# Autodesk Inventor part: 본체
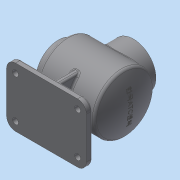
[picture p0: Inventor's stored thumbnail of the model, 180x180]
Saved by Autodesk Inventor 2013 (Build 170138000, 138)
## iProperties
Created: 2016-09
Part Number: 본체
Material: 일반
Document SubType Name: Modeling
Designer: dgall
Density: 1 g/cm^3
Author: dgall
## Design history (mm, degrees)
sketch "스케치1"
  geometry: L1 (-62, 0)-(60, 0); L2 (-62, 27)-(-47, 27); L3 (-47, 27)-(-47, 47); L4 (-47, 47)-(46.661, 47); L5 (-62, 27)-(-62, 38); L6 (-62, 38)-(-50, 38); L7 (-50, 38)-(-50, 50); L8 (-50, 50)-(48.562, 50); A1 r 115 centre (-55, 0) between (60, 0) and (48.562, 50); A2 r 112 centre (-55, 0) between (57, 0) and (46.661, 47); 2 further points
  constraints: 16 end point, 4 parallel, 4 point on circle, 3 perpendicular, 2 centre point, 2 point on line, 1 horizontal, 1 horizontal alignment, 1 midpoint
  dimensions: "d0" = 122 distance of L1.start L1.end; "d2" = 62 distance of L1.start point (0, 0); "d3" = 15 distance of L2.start L2.end; "d4" = 12 distance of L5.end L6.end; "d5" = 110 distance from line of L7 L1.end; "d6" = 76 diameter of L6 L1; "d7" = 54 diameter of L2 L1; "d8" = 100 diameter of L8 L1; "d9" = 94 diameter of L4 L1; "d10" = 230 diameter of A1; "d11" = 3 radial gap between concentric circles of A1 A2
revolve "회전1" sketch "스케치1" stored, may be unused: angle "d12" = 90 deg
sketch "스케치2" dims "d13" = 65
  geometry: C1 r 38 at (0, 0) reference; C2 r 27 at (0, 0) reference; 2 further points
  constraints: 2 vertical alignment, 1 coincident, 2 other
hole "구멍1" sketch "스케치2" at (0, 32.5) diameter "d15" = 3.242; stored, may be unused: countersink angle "d19" = 82 deg, drill point angle "d21" = 118 deg; dims "d16" = 8, "d17" = 3.023, "d18" = 2, "d20" = 10
node "작업 평면1"
sketch "스케치3" dims "d28" = 65
  geometry: C1 r 38 at (0, 0); C2 r 27 at (0, 0); 2 further points
  constraints: 2 centre point, 2 vertical alignment, 1 coincident, 2 other
  dimensions: "d26" = 76 diameter of C1; "d29" = 54 diameter of C2
extrude "돌출1" join sketch "스케치3" stored distance "d30" = 10; taper "d31" = 0 deg
extrude "돌출2" cut sketch "스케치3" distance "d32" = 61.5; taper "d33" = 0 deg
hole "구멍2" sketch "스케치3" diameter "d34" = 3.242; stored, may be unused: countersink angle "d38" = 82 deg, drill point angle "d40" = 118 deg; dims "d35" = 8, "d36" = 3.023, "d37" = 2, "d39" = 10
fillet "모깎기1" dims "d44" = 2
node "작업 평면2"
sketch "스케치4"
  geometry: L1 (67.5, 50)-(-67.5, 50); L2 (-67.5, 50)-(-67.5, -50); L3 (-67.5, -50)-(67.5, -50); L4 (67.5, -50)-(67.5, 50); 3 further points
  constraints: 8 end point, 2 midpoint, 2 parallel, 1 horizontal, 1 horizontal alignment, 1 perpendicular, 1 vertical alignment
  dimensions: "d46" = 135 distance of L2.end L3.end; "d48" = 100 distance of L3.end L1.start
extrude "돌출3" join sketch "스케치4" distance "d49" = 10; taper "d50" = 0 deg
fillet "모깎기2" dims "d51" = 15, "d52" = 5, "d53" = 3
sketch "스케치5"
  geometry: C1 r 5 at (-52.5, 35); C2 r 5 at (-52.5, -35); C3 r 5 at (52.5, -35); C4 r 5 at (52.5, 35); A1 r 15 centre (52.5, 35) between (67.5, 35) and (52.5, 50) reference; A2 r 15 centre (-52.5, 35) between (-52.5, 50) and (-67.5, 35) reference; A3 r 15 centre (-52.5, -35) between (-67.5, -35) and (-52.5, -50) reference; A4 r 15 centre (52.5, -35) between (52.5, -50) and (67.5, -35) reference; 1 further point
  constraints: 4 centre point, 4 coincident, 3 equal radius
  dimensions: "d54" = 10 diameter of C2
extrude "돌출4" cut sketch "스케치5" distance "d56" = 47.25; taper "d57" = 0 deg
sketch "스케치6"
  geometry: L1 (-72, 40)-(-72, 30) reference; L2 (-72, -30)-(-72, -40) reference; L3 (-72, 40)-(-72, 30) reference; L4 (-72, -30)-(-72, -40) reference; L5 (-72, -50)-(-72, -35) reference; L6 (-72, -35)-(-72, -50) reference; L7 (-72, -35)-(-72, 35) reference; L8 (-72, 50)-(-72, 35) reference; L9 (-72, 35)-(-72, 50) reference; L10 (-72, 35)-(-72, -35) reference; L11 (-30, 40)-(-72, 40); L12 (-30, -40)-(-72, -40); L13 (-72, 40)-(-72, -40); A1 r 50 centre (0, 0) between (-30, 40) and (-30, -40) reference; A2 r 50 centre (0, 0) between (-30, 40) and (-30, -40); 1 further point
  constraints: 6 end point, 4 point on circle, 3 perpendicular, 2 point on line, 1 centre point, 1 coincident, 1 concentric, 1 parallel
  dimensions: "d58" = 40 distance from line of point (0, 0) L12
extrude "돌출5" join sketch "스케치6" stored distance "d59" = 10; taper "d60" = 0 deg
sketch "스케치7"
  geometry: L1 (-45, -50)-(45.374, -50) reference; L2 (52.5, -72)-(-52.5, -72) reference; L3 (52.5, -72)-(67.5, -72) reference; L4 (67.5, -72)-(67.5, -82) reference; L5 (67.5, -82)-(52.5, -82) reference; L6 (52.5, -82)-(52.5, -72) reference; L7 (-67.5, -72)-(-52.5, -72) reference; L8 (-52.5, -72)-(-52.5, -82) reference; L9 (-52.5, -82)-(-67.5, -82) reference; L10 (-67.5, -82)-(-67.5, -72) reference; L11 (-40, -72)-(-37.988, -49); L12 (-37.988, -49)-(37.988, -49); L13 (37.988, -49)-(40, -72); L14 (-40, -72)-(40, -72); 3 further points
  constraints: 8 end point, 2 midpoint, 2 point on line, 2 vertical alignment, 1 equal length, 1 parallel, 1 perpendicular
  dimensions: "d61" = 95 deg angle of L3 L13; "d62" = 40 distance of L13.end point (0, -72); "d64" = 23 distance between parallel lines of L14 L12
extrude "돌출6" join sketch "스케치7" stored distance "d65" = 10; taper "d66" = 0 deg
fillet "모깎기3" dims "d67" = 3
fillet "모깎기4" dims "d68" = 3
chamfer "모따기1" distance "d69" = 1; stored, may be unused: second distance "d70" = 2, angle "d71" = 45 deg
node "작업 평면3"
sketch "스케치8"
  geometry: 2 further points
  constraints: 1 coincident, 1 other
feature "엠보싱1" sketch "스케치8" dims "d0" = 122, "d2" = 62, "d3" = 15, "d4" = 12, "d5" = 110, "d6" = 76, "d7" = 54, "d8" = 100, "d9" = 94, "d10" = 230, "d11" = 3, "d72" = 0.5, "d73" = 0
node "솔리드1"
pattern_circular "원형 패턴1" dims angle "d23" = 360 deg
pattern_circular "원형 패턴2" dims angle "d42" = 360 deg
node "투영된 루프1"
node "투영된 루프2"
node "투영된 루프3"
other parameters: "d25" = 65, "d45" = -147
